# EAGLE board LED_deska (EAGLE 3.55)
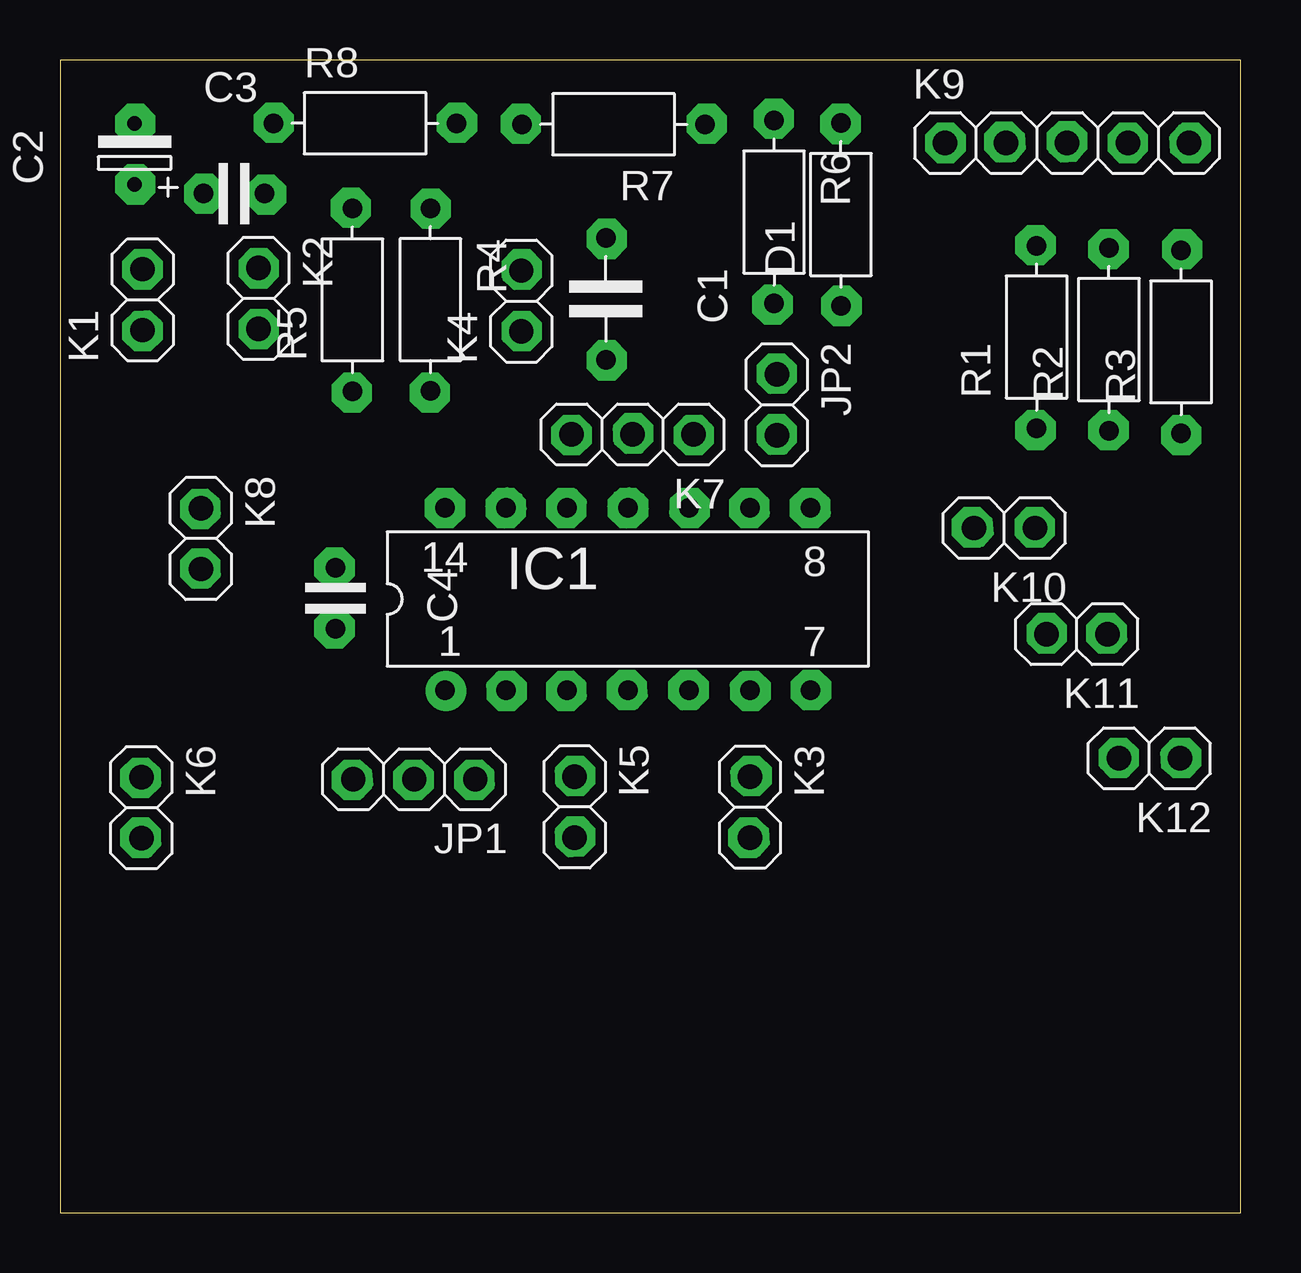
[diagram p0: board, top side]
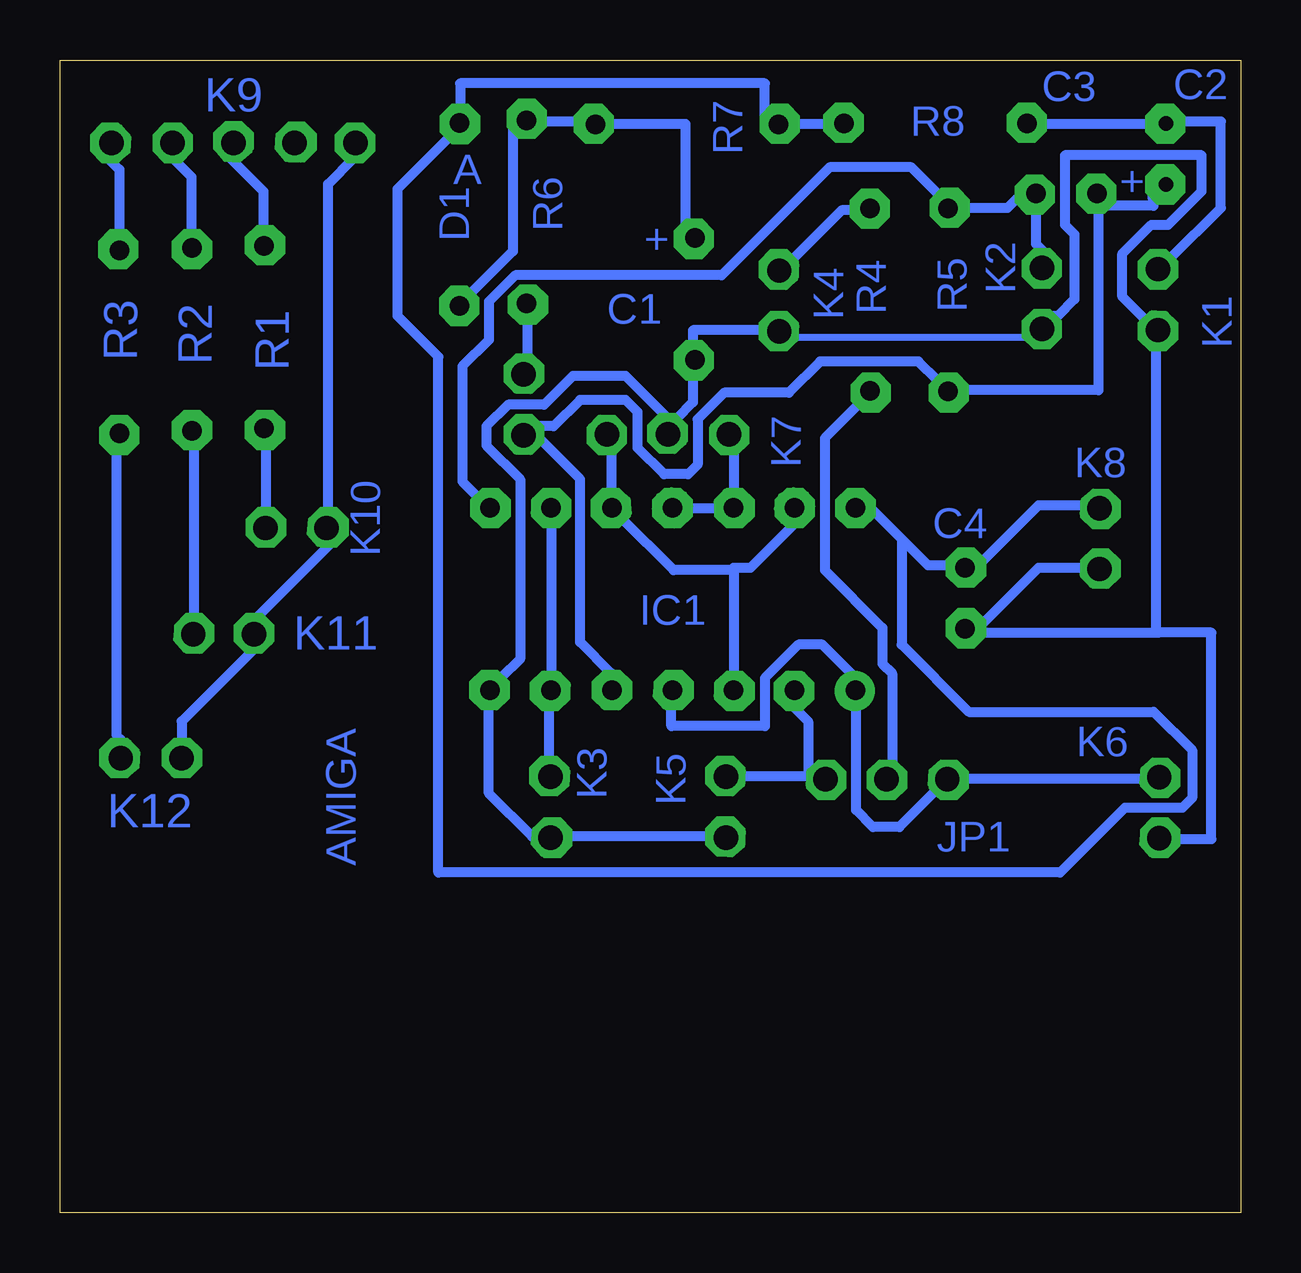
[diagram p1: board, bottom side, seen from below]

Size 49.19 x 48.06 mm. Coordinates in mm from the lower left corner, seen from the top.
Outline: 0,0 49.19,0 49.19,48.06 0,48.06 0,0
Copper layers used: Bottom

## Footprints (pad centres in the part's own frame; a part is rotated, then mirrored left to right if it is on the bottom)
5 = drill 0.813 pad 1.397 octagon:  -2.54,0;  2.54,0
-2,5 = drill 0.61 pad 1.27 octagon:  -1.27,0;  1.27,0
2,5 = drill 0.813 pad 1.397 octagon:  -1.27,0;  1.27,0
7,5 = drill 0.813 pad 1.397 octagon:  -3.81,0;  3.81,0
L14 = drill 0.813 pad 1.6 round:  -7.62,-3.81 | drill 0.813 pad 1.6 octagon:  -5.08,-3.81;  -2.54,-3.81;  0,-3.81;  2.54,-3.81;  5.08,-3.81;  7.62,-3.81;  7.62,3.81;  5.08,3.81;  2.54,3.81;  0,3.81;  -2.54,3.81;  -5.08,3.81;  -7.62,3.81
03 = drill 1.016 pad 1.6 octagon:  -2.54,0;  0,0;  2.54,0
02 = drill 1.016 pad 1.6 octagon:  -1.27,0;  1.27,0
05 = drill 1.016 pad 1.6 octagon:  -5.08,0;  -2.54,0;  0,0;  2.54,0;  5.08,0

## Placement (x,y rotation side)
C1  100uF  [5]  22.74,38.1 270 top
C2  2u2  [-2,5]  3.11,44.15 90 top
C3  100nF  [2,5]  7.25,42.49 0 top
C4  100nF  [2,5]  11.48,25.63 270 top
D1  KA222  [7,5]  32.54,41.62 90 top
IC1  7404  [L14]  23.66,25.59 0 top
JP1  [03]  14.76,18.08 180 top
JP2  [02]  29.87,33.68 270 top
K1  TL.RESET  [02]  3.44,38.07 90 top
K2  RESET  [02]  8.27,38.12 270 top
K3  /RESET  [02]  28.75,16.91 270 top
K4  LED_TURBO  [02]  19.22,38.01 90 top
K5  TURBO_OUT  [02]  21.44,16.92 270 top
K6  /TURBO_OUT  [02]  3.39,16.89 270 top
K7  TL._TURBO  [03]  23.86,32.45 180 top
K8  PINHD-1X2  [02]  5.87,28.11 270 top
K9  AMIGA_BOARD  [05]  41.96,44.6 0 top
K10  LED_HD  [02]  39.35,28.55 180 top
K11  LED_FLOPY  [02]  42.37,24.13 180 top
K12  LED_POWER  [02]  45.39,18.95 180 top
R1  Rx  [7,5]  40.69,36.51 90 top
R2  Rx  [7,5]  43.7,36.41 90 top
R3  Rx  [7,5]  46.71,36.31 90 top
R4  Rx  [7,5]  15.43,38.07 270 top
R5  33K  [7,5]  12.18,38.06 90 top
R6  1K  [7,5]  29.75,41.72 270 top
R7  47K  [7,5]  23.07,45.38 180 top
R8  100K  [7,5]  12.71,45.42 0 top

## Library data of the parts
C1-C4 D1 R1-R8 = DISCRETE
IC1 = 74XX
JP1 JP2 K1-K12 = PINHEAD

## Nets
S$22: K2.

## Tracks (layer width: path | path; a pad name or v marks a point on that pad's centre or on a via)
S$1
  Bottom 0.406: 28.72,28.79 28.72,22.39
S$2
  Bottom 0.406: 18.42,28.89 20.42,26.89 21.12,26.89 21.12,26.79 | 21.12,26.79 21.12,22.39 | 21.12,26.79 23.62,26.79 25.82,28.99
S$3
  Bottom 0.406: 26.22,31.79 26.22,30.09 26.32,30.09
S$4
  Bottom 0.406: 23.12,29.39 21.72,29.39
S$5
  Bottom 0.406: 16.12,22.39 17.42,23.69 18.42,23.69 19.82,22.29 19.82,20.29 23.72,20.29 23.72,21.19
S$6
  Bottom 0.406: 21.12,31.89 21.12,30.09
S$7
  Bottom 0.406: 17.12,45.39 18.72,45.39
S$8
  Bottom 0.406: 19.82,45.39 19.82,47.09 32.52,47.09 32.52,45.99
S$9
  Bottom 0.406: 23.12,41.09 23.12,45.39 26.32,45.39
S$10
  Bottom 0.406: 27.42,45.39 27.42,45.49 29.12,45.49
S$11
  Bottom 0.406: 30.32,45.49 30.32,40.09 32.12,38.29
S$12
  Bottom 0.406: 16.02,41.79 16.62,41.79 18.72,39.69
S$13
  Bottom 0.406: 2.92,39.79 0.82,41.89 0.82,45.49 2.62,45.49
S$14
  Bottom 0.406: 3.62,45.39 8.22,45.39
S$15
  Bottom 0.406: 2.62,15.59 1.22,15.59 1.22,24.19 3.42,24.19 3.52,24.19 | 10.92,24.19 3.52,24.19 | 3.52,24.19 3.52,36.09
S$16
  Bottom 0.406: 3.92,37.19 4.92,38.19 4.92,39.99 3.72,41.19 3.02,41.19 1.62,42.59 1.62,44.09 7.32,44.09 7.32,41.19 6.92,40.79 6.92,38.09 7.62,37.39 7.82,37.39
S$17
  Bottom 0.406: 8.22,40.09 8.52,40.39 8.52,41.79
S$18
  Bottom 0.406: 9.12,42.49 9.72,41.89 11.62,41.89
S$19
  Bottom 0.406: 3.74,42.93 3.63,41.98 5.7,41.98
S$20
  Bottom 0.406: 5.92,41.99 5.92,34.29 11.52,34.29
S$21
  Bottom 0.406: 29.72,37.29 29.72,35.59 29.92,35.59
S$22
  Bottom 0.3: 18.52,36.49 8.92,36.49 K2.
S$23
  Bottom 0.406: 19.82,36.79 22.82,36.79 22.82,36.29
S$24
  Bottom 0.406: 22.82,34.99 22.82,33.79 23.52,33.09
S$25
  Bottom 0.406: 26.22,22.49 27.52,23.79 27.52,30.59 29.22,32.29
S$26
  Bottom 0.406: 12.62,34.69 13.42,35.49 17.52,35.49 18.82,34.19 21.52,34.19 22.62,33.09 22.62,31.19 23.02,30.79 24.02,30.79 25.12,31.89 25.12,33.39 25.62,33.89 27.52,33.89 28.62,32.79 29.32,32.79
S$27
  Bottom 0.406: 28.72,21.19 28.82,21.09 28.82,18.89
S$28
  Bottom 0.406: 18.72,21.19 18.02,20.49 18.02,18.29
S$29
  Bottom 0.406: 18.02,18.19 20.82,18.19
S$30
  Bottom 0.406: 22.02,15.69 28.02,15.69
S$31
  Bottom 0.406: 29.52,15.69 31.32,17.49 31.32,21.09
S$32
  Bottom 0.406: 23.92,33.19 25.62,34.89 27.82,34.89 29.02,33.69 30.52,33.69 31.42,32.79 31.42,31.99 30.02,30.59 30.02,23.09 30.82,22.29
S$33
  Bottom 0.406: 6.52,29.49 8.42,29.49 10.82,27.09
S$34
  Bottom 0.406: 12.12,26.99 13.02,26.99 14.12,28.09 | 14.12,28.09 15.32,29.29 | 14.12,28.09 14.12,23.69 11.32,20.89 3.62,20.89 2.02,19.29 2.02,17.29 2.42,16.89 4.82,16.89 7.52,14.19 33.42,14.19 33.42,35.69 35.12,37.39 35.12,42.69 32.92,44.89
S$35
  Bottom 0.406: 6.62,26.89 8.42,26.89 10.82,24.49
S$36
  Bottom 0.406: 4.02,18.09 11.52,18.09 11.52,17.99 11.62,17.99
S$37
  Bottom 0.406: 12.72,17.59 14.22,16.09 15.32,16.09 16.02,16.79 16.02,21.09
S$38
  Bottom 0.406: 40.62,32.09 40.62,29.39
S$39
  Bottom 0.406: 43.62,32.09 43.62,24.89
S$40
  Bottom 0.406: 46.62,19.69 46.82,19.89 46.82,31.89
S$41
  Bottom 0.406: 37.92,27.89 41.02,24.79 41.12,24.79 41.12,24.69
S$42
  Bottom 0.406: 41.12,23.49 44.12,20.49 44.12,19.69
S$43
  Bottom 0.406: 47.12,43.89 46.72,43.49 46.72,40.79
S$44
  Bottom 0.406: 44.52,43.99 43.72,43.19 43.72,40.99
S$45
  Bottom 0.406: 42.12,43.99 40.72,42.59 40.72,40.99
S$46
  Bottom 0.406: 38.02,29.29 38.02,42.89 36.92,43.99
S$47
  Bottom 0.406: 12.52,42.39 13.72,43.59 17.12,43.59 21.62,39.09 30.22,39.09 31.32,37.99 31.32,36.39 32.42,35.29 32.42,30.49 31.82,29.89
S$48
  Bottom 0.406: 15.82,33.79 17.32,32.29 17.32,26.79 14.92,24.39 14.92,22.89 14.52,22.49 14.52,18.79
S$49  (via drill 0.25 pad 1.68)
  other vias: 32.52,45.39
S$50  (via drill 0.25 pad 1.68)
  other vias: 29.74,45.61
S$51  (via drill 0.25 pad 1.68)
  other vias: 26.95,45.4
S$52  (via drill 0.25 pad 1.68)
  other vias: 22.78,40.6
S$53  (via drill 0.25 pad 1.68)
  other vias: 19.2,45.4
S$54  (via drill 0.25 pad 1.68)
  other vias: 16.54,45.44
S$55  (via drill 0.25 pad 1.68)
  other vias: 8.91,45.44
S$56  (via drill 0.25 pad 1.68)
  other vias: 3.14,45.4
S$57  (via drill 0.25 pad 1.68)
  other vias: 3.14,42.87
S$58  (via drill 0.25 pad 1.68)
  other vias: 6.01,42.49
S$59  (via drill 0.25 pad 1.68)
  other vias: 8.58,42.45
S$60  (via drill 0.25 pad 1.68)
  other vias: 8.28,39.37
S$61  (via drill 0.25 pad 1.68)
  other vias: 8.28,36.84
S$62  (via drill 0.25 pad 1.68)
  other vias: 3.44,39.33
S$63  (via drill 0.25 pad 1.68)
  other vias: 3.44,36.76
S$64  (via drill 0.25 pad 1.68)
  other vias: 12.12,41.9
S$65  (via drill 0.25 pad 1.68)
  other vias: 15.45,41.86
S$66  (via drill 0.25 pad 1.68)
  other vias: 19.24,39.33
S$67  (via drill 0.25 pad 1.68)
  other vias: 19.24,36.76
S$68  (via drill 0.25 pad 1.68)
  other vias: 22.78,35.54
S$69  (via drill 0.25 pad 1.68)
  other vias: 32.56,37.81
S$70  (via drill 0.25 pad 1.68)
  other vias: 29.69,37.86
S$71  (via drill 0.25 pad 1.68)
  other vias: 29.86,34.99
S$72  (via drill 0.25 pad 1.68)
  other vias: 29.86,32.46
S$73  (via drill 0.25 pad 1.68)
  other vias: 26.41,32.42
S$74  (via drill 0.25 pad 1.68)
  other vias: 23.88,32.5
S$75  (via drill 0.25 pad 1.68)
  other vias: 21.31,32.42
S$76  (via drill 0.25 pad 1.68)
  other vias: 15.41,34.19
S$77  (via drill 0.25 pad 1.68)
  other vias: 12.16,34.19
S$78  (via drill 0.25 pad 1.68)
  other vias: 5.84,29.34
S$79  (via drill 0.25 pad 1.68)
  other vias: 5.84,26.86
S$80  (via drill 0.25 pad 1.68)
  other vias: 11.44,26.9
S$81  (via drill 0.25 pad 1.68)
  other vias: 16.04,29.38
S$82  (via drill 0.25 pad 1.68)
  other vias: 18.57,29.38
S$83  (via drill 0.25 pad 1.68)
  other vias: 21.09,29.38
S$84  (via drill 0.25 pad 1.68)
  other vias: 23.67,29.38
S$85  (via drill 0.25 pad 1.68)
  other vias: 26.24,29.38
S$86  (via drill 0.25 pad 1.68)
  other vias: 28.72,29.38
S$87  (via drill 0.25 pad 1.68)
  other vias: 31.25,29.38
S$88  (via drill 0.25 pad 1.68)
  other vias: 16.08,21.76
S$89  (via drill 0.25 pad 1.68)
  other vias: 11.44,24.37
S$90  (via drill 0.25 pad 1.68)
  other vias: 12.16,18.05
S$91  (via drill 0.25 pad 1.68)
  other vias: 14.73,18.05
S$92  (via drill 0.25 pad 1.68)
  other vias: 17.26,18.05
S$93  (via drill 0.25 pad 1.68)
  other vias: 21.47,18.22
S$94  (via drill 0.25 pad 1.68)
  other vias: 21.47,15.69
S$95  (via drill 0.25 pad 1.68)
  other vias: 28.81,18.22
S$96  (via drill 0.25 pad 1.68)
  other vias: 28.68,15.64
S$97  (via drill 0.25 pad 1.68)
  other vias: 3.35,18.13
S$98  (via drill 0.25 pad 1.68)
  other vias: 3.35,15.64
S$99  (via drill 0.25 pad 1.68)
  other vias: 18.61,21.76
S$100  (via drill 0.25 pad 1.68)
  other vias: 21.09,21.76
S$101  (via drill 0.25 pad 1.68)
  other vias: 23.62,21.8
S$102  (via drill 0.25 pad 1.68)
  other vias: 26.19,21.8
S$103  (via drill 0.25 pad 1.68)
  other vias: 28.77,21.76
S$104  (via drill 0.25 pad 1.68)
  other vias: 31.29,21.8
S$105  (via drill 0.25 pad 1.68)
  other vias: 40.65,32.63
S$106  (via drill 0.25 pad 1.68)
  other vias: 43.69,32.63
S$107  (via drill 0.25 pad 1.68)
  other vias: 46.72,32.42
S$108  (via drill 0.25 pad 1.68)
  other vias: 40.61,28.58
S$109  (via drill 0.25 pad 1.68)
  other vias: 38,28.58
S$110  (via drill 0.25 pad 1.68)
  other vias: 41.11,24.16
S$111  (via drill 0.25 pad 1.68)
  other vias: 43.6,24.16
S$112  (via drill 0.25 pad 1.68)
  other vias: 44.11,18.97
S$113  (via drill 0.25 pad 1.68)
  other vias: 46.72,18.97
S$114  (via drill 0.25 pad 1.68)
  other vias: 36.9,44.6
S$115  (via drill 0.25 pad 1.68)
  other vias: 39.34,44.64
S$116  (via drill 0.25 pad 1.68)
  other vias: 41.96,44.68
S$117  (via drill 0.25 pad 1.68)
  other vias: 44.49,44.6
S$118  (via drill 0.25 pad 1.68)
  other vias: 47.1,44.6
S$119  (via drill 0.25 pad 1.68)
  other vias: 46.76,40.17
S$120  (via drill 0.25 pad 1.68)
  other vias: 43.69,40.17
S$121  (via drill 0.25 pad 1.68)
  other vias: 40.65,40.34

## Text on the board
Bottom: C2 | C3 | R7 | K9 | R8 | R6 | + | A | D1 | K2 | R5 | R4 | K4 | + | K1 | R3 | C1 | R1 | R2 | K7 | K8 | K10 | C4 | IC1 | K11 | AMIGA | K6 | K5 | K3 | K12 | JP1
